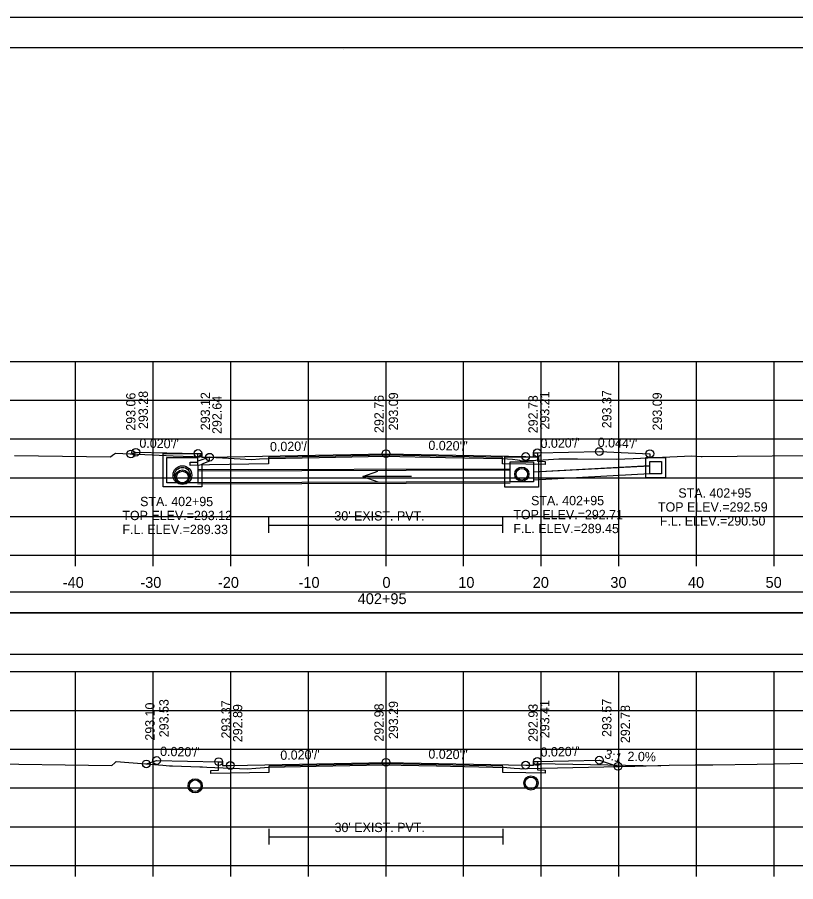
# Model space of a CAD drawing. Extents: x 1370538 to 1372872, y 376220 to 381127.
# Drawn here: x 1370661.1 to 1370761.4, y 376535.7 to 376647.1 of the extents above; entities that cross this region are included whole.
import ezdxf

# ---------------------------------------------------------------- set-up
doc = ezdxf.new("R2010")
doc.units = 0
for name, color, linetype in [('R_Border', 7, 'Continuous'), ('R_Border Notes', 7, 'Continuous'), ('R_Border PE', 7, 'Continuous'), ('R_Border Prem', 7, 'Continuous'), ('R_Dimension', 7, 'Continuous'), ('R_Fin Surface', 7, 'Continuous'), ('R_Grid', 7, 'Continuous'), ('R_No Plot', 7, 'Continuous'), ('R_Water', 7, 'Continuous'), ('R_Water Annot', 7, 'Continuous'), ('R_Xsect Elev', 7, 'Continuous'), ('R_Xsect Slope', 7, 'Continuous'), ('T_Detection Zones', 7, 'Continuous')]:
    doc.layers.add(name, color=color, linetype=linetype)

msp = doc.modelspace()

# ---------------------------------------------------------------- linework, layer by layer
at = {"layer": 'R_Border'}
for p, q in [((1370693.45, 376582.63), (1370693.45, 376580.63)), ((1370723.64, 376582.63), (1370723.64, 376580.63)), ((1370693.45, 376581.63), (1370723.64, 376581.63)), ((1370693.49, 376542.46), (1370693.49, 376540.46)), ((1370723.67, 376542.46), (1370723.67, 376540.46)), ((1370693.49, 376541.46), (1370723.67, 376541.46))]:
    msp.add_line(p, q, dxfattribs=at)
for points in [[(1370728.11, 376590.96), (1370728.11, 376589.87), (1370729.11, 376589.85), (1370729.11, 376589.43), (1370726.61, 376589.48), (1370723.64, 376589.54), (1370723.64, 376590.37), (1370708.61, 376590.67), (1370693.45, 376590.37), (1370693.45, 376589.54), (1370685.87, 376589.39), (1370683.37, 376589.34), (1370683.37, 376589.75), (1370684.37, 376589.77), (1370684.37, 376590.87)], [(1370728.11, 376551.17), (1370728.11, 376550.07), (1370729.11, 376550.05), (1370729.11, 376549.64), (1370726.61, 376549.69), (1370723.67, 376549.74), (1370723.67, 376550.58), (1370708.61, 376550.88), (1370693.49, 376550.57), (1370693.49, 376549.74), (1370688.54, 376549.65), (1370686.04, 376549.6), (1370686.04, 376550.01), (1370687.04, 376550.03), (1370687.04, 376551.13)]]:
    msp.add_lwpolyline(points, dxfattribs=at)
at = {"layer": 'R_Border Notes'}
for p, q in [((1370550.61, 376643.21), (1370866.79, 376643.21)), ((1370703.13, 376642.95), (1370703.13, 376642.95)), ((1370703.13, 376642.95), (1370703.13, 376642.95))]:
    msp.add_line(p, q, dxfattribs=at)
at = {"layer": 'R_Border Prem'}
for p, q in [((1370558.61, 376577.75), (1370858.61, 376577.75)), ((1370668.61, 376576.35), (1370668.61, 376577.75)), ((1370678.61, 376576.35), (1370678.61, 376577.75)), ((1370688.61, 376576.35), (1370688.61, 376577.75)), ((1370698.61, 376576.35), (1370698.61, 376577.75)), ((1370708.61, 376576.35), (1370708.61, 376577.75)), ((1370718.61, 376576.35), (1370718.61, 376577.75)), ((1370728.61, 376576.35), (1370728.61, 376577.75)), ((1370738.61, 376576.35), (1370738.61, 376577.75)), ((1370748.61, 376576.35), (1370748.61, 376577.75)), ((1370758.61, 376576.35), (1370758.61, 376577.75)), ((1370558.61, 376537.75), (1370858.61, 376537.75)), ((1370668.61, 376536.35), (1370668.61, 376537.75)), ((1370678.61, 376536.35), (1370678.61, 376537.75)), ((1370688.61, 376536.35), (1370688.61, 376537.75)), ((1370698.61, 376536.35), (1370698.61, 376537.75)), ((1370708.61, 376536.35), (1370708.61, 376537.75)), ((1370718.61, 376536.35), (1370718.61, 376537.75)), ((1370728.61, 376536.35), (1370728.61, 376537.75)), ((1370738.61, 376536.35), (1370738.61, 376537.75)), ((1370748.61, 376536.35), (1370748.61, 376537.75)), ((1370758.61, 376536.35), (1370758.61, 376537.75))]:
    msp.add_line(p, q, dxfattribs=at)
at = {"layer": 'R_Dimension'}
for points in [[(1370660.72, 376590.6), (1370673.12, 376590.44), (1370673.38, 376590.65), (1370673.75, 376590.9), (1370678.48, 376590.69), (1370681.17, 376590.55), (1370683.75, 376590.48), (1370684.93, 376590.44), (1370687.54, 376590.3), (1370691.31, 376590.11), (1370692.29, 376590.17), (1370693.45, 376590.24), (1370700, 376590.37), (1370708.41, 376590.52), (1370716.26, 376590.35), (1370723.64, 376590.21), (1370724.9, 376590.12), (1370725.56, 376590.07), (1370725.8, 376590.02), (1370725.98, 376589.92), (1370728.86, 376590.07), (1370730.9, 376590.17), (1370733.29, 376590.17), (1370738.32, 376590.15), (1370740.45, 376590.23), (1370748.03, 376590.57), (1370749.22, 376590.5), (1370749.36, 376590.49), (1370758.37, 376590.57), (1370768.52, 376590.65)], [(1370655.22, 376550.9), (1370673.29, 376550.65), (1370673.66, 376550.97), (1370673.84, 376551.15), (1370679.85, 376550.69), (1370680.72, 376550.6), (1370681.1, 376550.59), (1370684.61, 376550.49), (1370684.94, 376550.48), (1370685.52, 376550.45), (1370690.74, 376550.2), (1370691.82, 376550.3), (1370693.49, 376550.42), (1370699.6, 376550.55), (1370708.29, 376550.73), (1370715.12, 376550.61), (1370724.19, 376550.38), (1370725.12, 376550.28), (1370725.84, 376550.24), (1370726.01, 376550.22), (1370726.72, 376550.24), (1370740.68, 376550.58), (1370745.08, 376550.69), (1370748.47, 376550.75), (1370750.73, 376550.74), (1370756.45, 376550.8), (1370764.92, 376551)]]:
    msp.add_lwpolyline(points, dxfattribs=at)
at = {"layer": 'R_Fin Surface'}
msp.add_line((1370742.61, 376590.84), (1370742.61, 376590.33), dxfattribs=at)
for points in [[(1370675.73, 376590.81), (1370676.37, 376591.03), (1370684.37, 376590.87), (1370684.87, 376590.87), (1370684.87, 376590.37), (1370685.87, 376590.39), (1370708.61, 376590.84), (1370726.61, 376590.48), (1370727.61, 376590.46), (1370727.61, 376590.96), (1370728.11, 376590.96), (1370736.11, 376591.12), (1370742.61, 376590.84)], [(1370677.73, 376550.85), (1370679.04, 376551.29), (1370687.04, 376551.13), (1370687.54, 376551.13), (1370687.54, 376550.63), (1370688.54, 376550.65), (1370708.61, 376551.05), (1370726.61, 376550.69), (1370727.61, 376550.67), (1370727.61, 376551.17), (1370728.11, 376551.17), (1370736.11, 376551.33), (1370738.5, 376550.53)]]:
    msp.add_lwpolyline(points, dxfattribs=at)
at = {"layer": 'R_Grid'}
for p, q in [((1370558.61, 376602.75), (1370858.61, 376602.75)), ((1370668.61, 376577.75), (1370668.61, 376602.75)), ((1370678.61, 376577.75), (1370678.61, 376602.75)), ((1370688.61, 376577.75), (1370688.61, 376602.75)), ((1370698.61, 376577.75), (1370698.61, 376602.75)), ((1370708.61, 376577.75), (1370708.61, 376602.75)), ((1370718.61, 376577.75), (1370718.61, 376602.75)), ((1370728.61, 376577.75), (1370728.61, 376602.75)), ((1370738.61, 376577.75), (1370738.61, 376602.75)), ((1370748.61, 376577.75), (1370748.61, 376602.75)), ((1370758.61, 376577.75), (1370758.61, 376602.75)), ((1370558.61, 376597.75), (1370858.61, 376597.75)), ((1370558.61, 376592.75), (1370858.61, 376592.75)), ((1370558.61, 376587.75), (1370858.61, 376587.75)), ((1370558.61, 376582.75), (1370858.61, 376582.75)), ((1370558.61, 376577.75), (1370858.61, 376577.75)), ((1370558.61, 376562.75), (1370858.61, 376562.75)), ((1370668.61, 376537.75), (1370668.61, 376562.75)), ((1370678.61, 376537.75), (1370678.61, 376562.75)), ((1370688.61, 376537.75), (1370688.61, 376562.75)), ((1370698.61, 376537.75), (1370698.61, 376562.75)), ((1370708.61, 376537.75), (1370708.61, 376562.75)), ((1370718.61, 376537.75), (1370718.61, 376562.75)), ((1370728.61, 376537.75), (1370728.61, 376562.75)), ((1370738.61, 376537.75), (1370738.61, 376562.75)), ((1370748.61, 376537.75), (1370748.61, 376562.75)), ((1370758.61, 376537.75), (1370758.61, 376562.75)), ((1370558.61, 376557.75), (1370858.61, 376557.75)), ((1370558.61, 376552.75), (1370858.61, 376552.75)), ((1370558.61, 376547.75), (1370858.61, 376547.75)), ((1370558.61, 376542.75), (1370858.61, 376542.75)), ((1370558.61, 376537.75), (1370858.61, 376537.75))]:
    msp.add_line(p, q, dxfattribs=at)
at = {"layer": 'R_No Plot'}
for p, q in [((1370538.21, 376647.11), (1370871.54, 376647.11)), ((1370742.61, 376589.26), (1370727.61, 376588.46)), ((1370724.61, 376588.87), (1370684.37, 376588.75)), ((1370742.61, 376588.25), (1370727.61, 376587.45)), ((1370724.61, 376587.04), (1370684.37, 376586.92))]:
    msp.add_line(p, q, dxfattribs=at)
for points in [[(1370538.2, 376647.11), (1370871.54, 376647.11), (1370871.54, 376433.77), (1370538.2, 376433.77)], [(1370784.53, 376643.21), (1370784.53, 376633.33), (1370820.26, 376633.33), (1370820.26, 376630.41), (1370843.46, 376630.41), (1370843.46, 376606.08), (1370866.79, 376606.08), (1370866.79, 376437.75), (1370550.61, 376437.75), (1370550.61, 376643.21)]]:
    msp.add_lwpolyline(points, close=True, dxfattribs=at)
for centre, radius in [((1370675.73, 376590.81), 0.5), ((1370676.37, 376591.03), 0.5), ((1370684.37, 376590.87), 0.5), ((1370708.61, 376590.84), 0.5), ((1370728.11, 376590.96), 0.5), ((1370736.11, 376591.12), 0.5), ((1370742.61, 376590.84), 0.5), ((1370685.87, 376590.39), 0.5), ((1370726.61, 376590.48), 0.5), ((1370682.37, 376588.08), 1.21), ((1370726.11, 376588.2), 0.917), ((1370682.37, 376587.83), 0.917), ((1370677.73, 376550.85), 0.5), ((1370679.04, 376551.29), 0.5), ((1370687.04, 376551.13), 0.5), ((1370688.54, 376550.65), 0.5), ((1370708.61, 376551.05), 0.5), ((1370726.61, 376550.69), 0.5), ((1370728.11, 376551.17), 0.5), ((1370736.11, 376551.33), 0.5), ((1370738.5, 376550.53), 0.5), ((1370684.02, 376548.03), 0.917), ((1370727.28, 376548.4), 0.917)]:
    msp.add_circle(centre, radius, dxfattribs=at)
at = {"layer": 'R_Water'}
for p, q in [((1370679.87, 376590.87), (1370684.62, 376590.87)), ((1370679.87, 376589.37), (1370679.87, 376590.87)), ((1370680.37, 376589.37), (1370680.37, 376590.37)), ((1370680.37, 376590.37), (1370684.37, 376590.37)), ((1370684.7, 376590.7), (1370684.37, 376590.37)), ((1370685.87, 376590.39), (1370684.37, 376589.87)), ((1370684.7, 376590.7), (1370684.62, 376590.87)), ((1370684.37, 376589.37), (1370684.37, 376589.87)), ((1370685.87, 376589.86), (1370684.87, 376589.51)), ((1370684.87, 376589.37), (1370684.87, 376589.51)), ((1370742.61, 376589.25), (1370727.61, 376588.45)), ((1370724.61, 376588.7), (1370684.37, 376588.58)), ((1370742.61, 376588.25), (1370727.61, 376587.45)), ((1370724.61, 376587.2), (1370684.37, 376587.08)), ((1370727.61, 376550.67), (1370728.11, 376550.92)), ((1370728.11, 376550.92), (1370744.02, 376550.6))]:
    msp.add_line(p, q, dxfattribs=at)
for points in [[(1370685.87, 376589.86), (1370685.87, 376590.39)], [(1370684.87, 376589.37), (1370684.87, 376586.58), (1370682.37, 376586.58), (1370679.87, 376586.58), (1370679.87, 376589.37)], [(1370684.37, 376589.37), (1370684.37, 376587.08), (1370682.37, 376587.08), (1370680.37, 376587.08), (1370680.37, 376589.37)]]:
    msp.add_lwpolyline(points, dxfattribs=at)
for points in [[(1370726.11, 376590.46), (1370728.27, 376590.46), (1370728.27, 376586.54), (1370726.11, 376586.54), (1370723.94, 376586.54), (1370723.94, 376590.46)], [(1370743.36, 376590.34), (1370744.61, 376590.34), (1370744.61, 376587.75), (1370743.36, 376587.75), (1370742.11, 376587.75), (1370742.11, 376590.34)], [(1370726.11, 376589.8), (1370727.61, 376589.8), (1370727.61, 376587.2), (1370726.11, 376587.2), (1370724.61, 376587.2), (1370724.61, 376589.8)], [(1370743.36, 376589.84), (1370744.11, 376589.84), (1370744.11, 376588.25), (1370743.36, 376588.25), (1370742.61, 376588.25), (1370742.61, 376589.84)]]:
    msp.add_lwpolyline(points, close=True, dxfattribs=at)
for centre, radius in [((1370682.37, 376588.08), 1), ((1370682.37, 376587.83), 0.75), ((1370726.11, 376588.2), 0.75), ((1370727.28, 376548.4), 0.75), ((1370684.02, 376548.03), 0.75)]:
    msp.add_circle(centre, radius, dxfattribs=at)
at = {"layer": 'R_Water Annot'}
for p, q in [((1370705.61, 376587.9), (1370707.54, 376588.6)), ((1370711.9, 376587.91), (1370705.61, 376587.9)), ((1370705.61, 376587.9), (1370707.54, 376587.2))]:
    msp.add_line(p, q, dxfattribs=at)
at = {"layer": 'R_Xsect Elev'}
for p, q in [((1370708.61, 376590.51), (1370708.61, 376600.51)), ((1370708.61, 376550.73), (1370708.61, 376560.73))]:
    msp.add_line(p, q, dxfattribs=at)
at = {"layer": 'T_Detection Zones'}
for points in [[(1370552.62, 376570.31), (1370864.59, 376570.31), (1370864.59, 376573.01), (1370552.62, 376573.01)], [(1370552.62, 376564.98), (1370864.59, 376564.98), (1370864.59, 376570.31), (1370552.62, 376570.31)]]:
    msp.add_lwpolyline(points, close=True, dxfattribs=at)

# ---------------------------------------------------------------- texts
at = {"layer": 'R_Border PE'}
for s, p in [('-40', (1370666.95, 376573.55)), ('-30', (1370676.95, 376573.55)), ('-20', (1370686.95, 376573.55)), ('-10', (1370697.34, 376573.55)), ('0', (1370708.15, 376573.55)), ('10', (1370717.92, 376573.55)), ('20', (1370727.52, 376573.55)), ('30', (1370737.52, 376573.55)), ('40', (1370747.52, 376573.55)), ('50', (1370757.52, 376573.55)), ('402+95', (1370704.96, 376571.45))]:
    msp.add_text(s, height=1.4, dxfattribs=at).set_placement(p)
at = {"layer": 'R_Water'}
for p in [(1370701.95, 376582.23), (1370701.98, 376542.06)]:
    msp.add_text("30' EXIST. PVT.", height=1.2, dxfattribs=at).set_placement(p)
at = {"layer": 'R_Water Annot'}
for s, p in [('STA. 402+95', (1370746.28, 376585.18)), ('STA. 402+95', (1370676.92, 376584.08)), ('STA. 402+95', (1370727.3, 376584.2)), ('TOP ELEV.=292.59', (1370743.65, 376583.38)), ('TOP ELEV.=293.12', (1370674.63, 376582.28)), ('TOP ELEV.=292.71', (1370725.01, 376582.4)), ('F.L. ELEV.=290.50', (1370743.9, 376581.58)), ('F.L. ELEV.=289.33', (1370674.64, 376580.48)), ('F.L. ELEV.=289.45', (1370725.02, 376580.6))]:
    msp.add_text(s, height=1.2, dxfattribs=at).set_placement(p)
at = {"layer": 'R_Xsect Elev'}
for s, rotation, p in [('293.06', 90, (1370676.32, 376593.81)), ('293.28', 90, (1370677.92, 376594.03)), ('293.12', 90, (1370685.92, 376593.87)), ('292.64', 90, (1370687.42, 376593.39)), ('292.76', 90, (1370708.31, 376593.51)), ('293.09', 90, (1370710.16, 376593.84)), ('292.73', 90, (1370728.16, 376593.48)), ('293.21', 90, (1370729.66, 376593.96)), ('293.37', 90, (1370737.66, 376594.12)), ('293.09', 90, (1370744.16, 376593.84)), ('293.53', 90, (1370680.59, 376554.29)), ('293.37', 90, (1370688.59, 376554.13)), ('293.41', 90, (1370729.66, 376554.17)), ('293.57', 90, (1370737.66, 376554.33)), ('293.10', 90, (1370678.78, 376553.85)), ('292.89', 90, (1370690.09, 376553.65)), ('292.98', 90, (1370708.31, 376553.73)), ('293.29', 90, (1370710.16, 376554.05)), ('292.93', 90, (1370728.16, 376553.69)), ('292.78', 90, (1370740.05, 376553.53)), ('2.0%', 358.8542, (1370739.72, 376551.24))]:
    msp.add_text(s, height=1.2, rotation=rotation, dxfattribs=at).set_placement(p)
at = {"layer": 'R_Xsect Slope'}
for s, rotation, p in [("0.020'/'", 358.8542, (1370676.82, 376591.62)), ("0.020'/'", 1.1458, (1370693.67, 376591.14)), ("0.020'/'", 358.8542, (1370714.06, 376591.33)), ("0.020'/'", 1.1458, (1370728.53, 376591.57)), ("0.044'/'", 357.4886, (1370735.87, 376591.73)), ("0.020'/'", 358.8542, (1370679.49, 376551.88)), ("0.020'/'", 1.1458, (1370695, 376551.37)), ("0.020'/'", 358.8542, (1370714.06, 376551.54)), ("0.020'/'", 1.1458, (1370728.53, 376551.78)), ('3:1', 341.5651, (1370736.67, 376551.66))]:
    msp.add_text(s, height=1.2, rotation=rotation, dxfattribs=at).set_placement(p)

doc.saveas('drawing.dxf')
